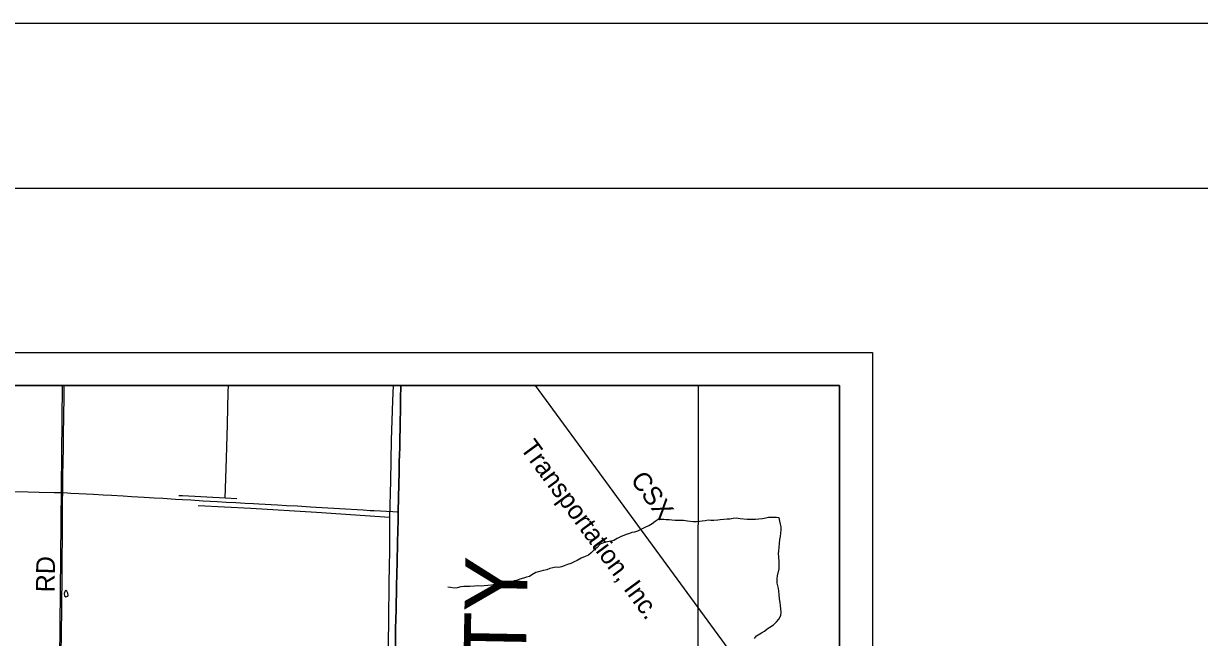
# Model space of a CAD drawing. Extents: x 0 to 34, y 0 to 22.
# Drawn here: x 6.42 to 9.993, y 20.135 to 22 of the extents above; entities that cross this region are included whole.
import ezdxf

# ---------------------------------------------------------------- set-up
doc = ezdxf.new("R2010")
doc.units = 0
for name, color, linetype in [('GM_X_City_Street', 7, 'Continuous'), ('GM_X_County_Road', 7, 'Continuous'), ('GM_X_County_Text', 7, 'Continuous'), ('GM_X_Minor_Lake', 7, 'Continuous'), ('GM_X_Minor_River', 7, 'Continuous'), ('GM_X_Rail_Line', 7, 'Continuous'), ('GM_X_Rail_Line_Text', 7, 'Continuous'), ('GM_X_Township_Road', 7, 'Continuous'), ('GM_X_Township_Road_Text', 7, 'Continuous'), ('GM_X_US_Route', 7, 'Continuous'), ('SH_Border', 7, 'Continuous'), ('SH_Cut_Line', 7, 'Continuous'), ('SH_Data', 7, 'Continuous')]:
    doc.layers.add(name, color=color, linetype=linetype)

msp = doc.modelspace()

# ---------------------------------------------------------------- linework, layer by layer
at = {"layer": 'GM_X_City_Street'}
msp.add_lwpolyline([(6.5392, 20.9), (5.527, 20.9), (5.5144, 20.0832), (6.5307, 20.0674)], close=True, dxfattribs=at)
at = {"layer": 'GM_X_County_Road'}
for points in [[(7.559, 20.516), (7.5591, 20.5235), (7.5596, 20.5509), (7.561, 20.6068), (7.5616, 20.6298), (7.5625, 20.6684), (7.563, 20.6883), (7.5638, 20.7125), (7.5655, 20.7958), (7.5659, 20.8188), (7.5659, 20.8449), (7.5661, 20.8636), (7.5668, 20.8953), (7.5669, 20.9)], [(7.5482, 19.9914), (7.5483, 19.9933), (7.5491, 20.0362), (7.5506, 20.1015), (7.5514, 20.1605), (7.5521, 20.1904), (7.5528, 20.2173), (7.5543, 20.2911), (7.5548, 20.3278), (7.556, 20.3619), (7.5564, 20.3806), (7.5567, 20.4036), (7.5571, 20.4228), (7.5579, 20.4589), (7.5585, 20.4894), (7.559, 20.516)]]:
    msp.add_lwpolyline(points, dxfattribs=at)
at = {"layer": 'GM_X_Minor_Lake'}
msp.add_line((6.5563, 20.2631), (6.5549, 20.2696), dxfattribs=at)
msp.add_lwpolyline([(6.5549, 20.2696), (6.5524, 20.2749), (6.549, 20.2773), (6.5467, 20.2758), (6.5435, 20.2683), (6.5448, 20.2611), (6.5493, 20.2579), (6.555, 20.2601), (6.5563, 20.2631)], dxfattribs=at)
at = {"layer": 'GM_X_Minor_River'}
for points in [[(7.0332, 20.5574), (7.0369, 20.678), (7.0407, 20.783), (7.0427, 20.8813), (7.0434, 20.9)], [(7.5437, 20.9), (7.5419, 20.8536), (7.5371, 20.7342), (7.5355, 20.6109), (7.5328, 20.4994), (7.5329, 20.3973), (7.5305, 20.3017), (7.5295, 20.186), (7.5269, 20.0494), (7.5234, 19.925), (7.5204, 19.8192)], [(7.0683, 20.5558), (7.0332, 20.5574), (6.9035, 20.5651), (6.8925, 20.5654)], [(7.5328, 20.4994), (7.3108, 20.5139), (7.1115, 20.5263), (6.9515, 20.5343)], [(8.7202, 20.231), (8.719, 20.2409), (8.7174, 20.2519), (8.7162, 20.2648), (8.7154, 20.275), (8.7139, 20.2838), (8.712, 20.2913), (8.7108, 20.2993), (8.7107, 20.3134), (8.7118, 20.3217), (8.7159, 20.3426), (8.7163, 20.3529), (8.7159, 20.3631), (8.715, 20.3802), (8.7146, 20.3885), (8.715, 20.398), (8.7161, 20.4075), (8.7186, 20.4318), (8.7209, 20.4417), (8.7223, 20.4619), (8.7227, 20.4706), (8.7207, 20.4785), (8.7188, 20.4876), (8.7161, 20.4979), (8.7085, 20.499), (8.7009, 20.4993), (8.693, 20.4989), (8.6842, 20.4992), (8.6755, 20.4973), (8.6653, 20.495), (8.6543, 20.4938), (8.6444, 20.4929), (8.6292, 20.4925), (8.6194, 20.4932), (8.5977, 20.4954), (8.5856, 20.4972), (8.5769, 20.4964), (8.5666, 20.4944), (8.5583, 20.494), (8.5484, 20.4932), (8.5374, 20.4916), (8.5298, 20.4908), (8.5181, 20.4896), (8.5086, 20.4903), (8.5002, 20.491), (8.4911, 20.4891), (8.465, 20.4863), (8.4555, 20.4855), (8.438, 20.4881), (8.4262, 20.4895), (8.4179, 20.4899), (8.4103, 20.4902), (8.4004, 20.4901), (8.3898, 20.4908), (8.3822, 20.4919), (8.3735, 20.4923), (8.3659, 20.4926), (8.3568, 20.493), (8.3484, 20.4929), (8.3393, 20.4872), (8.3306, 20.4803), (8.32, 20.4734), (8.3125, 20.4703), (8.3038, 20.4665), (8.2962, 20.4626), (8.2863, 20.458), (8.2765, 20.4549), (8.2689, 20.4534), (8.2613, 20.4507), (8.2511, 20.4472), (8.2344, 20.4403), (8.2238, 20.4349), (8.214, 20.4288), (8.2052, 20.4269), (8.195, 20.4253), (8.1829, 20.4222), (8.173, 20.418), (8.1636, 20.4084), (8.1549, 20.4015), (8.1454, 20.392), (8.1371, 20.3851), (8.1272, 20.3809), (8.1151, 20.3755), (8.103, 20.3686), (8.0939, 20.3644), (8.0829, 20.3598), (8.0735, 20.3563), (8.0636, 20.3525), (8.0549, 20.349), (8.0465, 20.3474), (8.0363, 20.3478), (8.0283, 20.3462), (8.0196, 20.3446), (8.0101, 20.3404), (7.9995, 20.3381), (7.9851, 20.3342), (7.9772, 20.3315), (7.965, 20.325), (7.9575, 20.3196), (7.9488, 20.3173), (7.9397, 20.3146)], [(7.9397, 20.3146), (7.9287, 20.3115), (7.9188, 20.308), (7.9112, 20.3065), (7.9006, 20.303), (7.8908, 20.2999), (7.8805, 20.2976), (7.8714, 20.2976), (7.8635, 20.2971), (7.8513, 20.2959), (7.8426, 20.2936), (7.8312, 20.292), (7.8198, 20.2912), (7.8111, 20.2908), (7.8001, 20.2915), (7.7902, 20.2907), (7.7766, 20.2895), (7.7663, 20.2898), (7.758, 20.2894), (7.7489, 20.2882), (7.7379, 20.2851), (7.7292, 20.2847), (7.7178, 20.2861), (7.7098, 20.2872)], [(8.6416, 20.1315), (8.6476, 20.1395), (8.6628, 20.1491), (8.6723, 20.1541), (8.6802, 20.161), (8.6878, 20.1656), (8.6987, 20.1725), (8.7086, 20.182), (8.7158, 20.19), (8.7218, 20.2018), (8.7229, 20.2117), (8.7217, 20.2216), (8.7202, 20.231)]]:
    msp.add_lwpolyline(points, dxfattribs=at)
at = {"layer": 'GM_X_Rail_Line'}
msp.add_lwpolyline([(8.9, 19.6389), (8.8604, 19.6932), (8.4181, 20.2972), (7.9759, 20.9)], dxfattribs=at)
at = {"layer": 'GM_X_Township_Road'}
msp.add_line((8.4697, 19.9905), (8.4711, 20.9), dxfattribs=at)
for points in [[(6.5395, 20.5746), (6.54, 20.6223), (6.5409, 20.6713), (6.5418, 20.7066), (6.542, 20.7127), (6.5423, 20.7526), (6.543, 20.8042), (6.5432, 20.8223), (6.5436, 20.8517), (6.5439, 20.8797), (6.5443, 20.9)], [(6.3942, 20.5779), (6.434, 20.5768), (6.4675, 20.5762), (6.5148, 20.575), (6.5353, 20.5747), (6.5395, 20.5746)], [(6.535, 20.0889), (6.5357, 20.1441), (6.536, 20.1628), (6.5361, 20.1753), (6.5364, 20.1945), (6.5366, 20.2031), (6.5367, 20.2127), (6.5367, 20.2169), (6.5367, 20.2249), (6.5371, 20.2456), (6.5373, 20.2698), (6.5375, 20.281), (6.5378, 20.3338), (6.5381, 20.382), (6.5381, 20.3851), (6.5384, 20.4274), (6.5385, 20.4349), (6.5386, 20.4541), (6.5389, 20.47), (6.5389, 20.4902), (6.5391, 20.5033), (6.5391, 20.5207), (6.5391, 20.533), (6.5393, 20.5579), (6.5395, 20.5685), (6.5395, 20.5746)], [(6.5395, 20.5746), (6.5538, 20.5739), (6.5638, 20.5735), (6.5886, 20.5721), (6.6333, 20.5695), (6.6625, 20.5677), (6.6873, 20.5666), (6.7233, 20.5644), (6.7482, 20.5631), (6.7871, 20.561), (6.8175, 20.559), (6.8436, 20.5574), (6.8821, 20.555), (6.9038, 20.5537), (6.9293, 20.5523), (6.9659, 20.5498), (7.0088, 20.5475), (7.0361, 20.5459), (7.0653, 20.5443), (7.0938, 20.5427), (7.1193, 20.5416), (7.1355, 20.5408), (7.1926, 20.5377), (7.2193, 20.536), (7.2528, 20.5342), (7.2919, 20.5318), (7.3801, 20.5267), (7.4527, 20.5221), (7.4732, 20.5206), (7.4856, 20.5199), (7.5421, 20.5168), (7.5554, 20.5162), (7.559, 20.516)]]:
    msp.add_lwpolyline(points, dxfattribs=at)
at = {"layer": 'GM_X_US_Route'}
for points in [[(7.5504, 20.102), (7.5511, 20.1611), (7.5519, 20.1909), (7.5526, 20.2178), (7.5541, 20.2916), (7.5545, 20.3283), (7.5557, 20.3625), (7.5562, 20.3811), (7.5565, 20.4041), (7.5569, 20.4234), (7.5577, 20.4595), (7.5583, 20.4899), (7.5588, 20.5166), (7.5589, 20.5241), (7.5593, 20.5515), (7.5608, 20.6074), (7.5614, 20.6304), (7.5623, 20.6689), (7.5628, 20.6888), (7.5635, 20.7131), (7.5652, 20.7964), (7.5656, 20.8193), (7.5657, 20.8455), (7.5659, 20.8641), (7.5666, 20.8958), (7.5667, 20.9), (2.1, 20.9)], [(8.9, 14.5091), (8.9, 20.9), (7.5667, 20.9), (7.5666, 20.8958), (7.5659, 20.8641), (7.5657, 20.8455), (7.5656, 20.8193), (7.5652, 20.7964), (7.5635, 20.7131), (7.5628, 20.6888), (7.5623, 20.6689), (7.5614, 20.6304), (7.5608, 20.6074), (7.5593, 20.5515), (7.5589, 20.5241), (7.5588, 20.5166), (7.5583, 20.4899), (7.5577, 20.4595), (7.5569, 20.4234), (7.5565, 20.4041), (7.5562, 20.3811), (7.5557, 20.3625), (7.5545, 20.3283), (7.5541, 20.2916), (7.5526, 20.2178), (7.5519, 20.1909), (7.5511, 20.1611), (7.5504, 20.102)]]:
    msp.add_lwpolyline(points, dxfattribs=at)
at = {"layer": 'SH_Border'}
msp.add_lwpolyline([(1.5, 21.5), (33.5, 21.5), (33.5, 0.5), (1.5, 0.5)], close=True, dxfattribs=at)
at = {"layer": 'SH_Cut_Line'}
msp.add_lwpolyline([(0, 0), (34, 0), (34, 22), (0, 22)], close=True, dxfattribs=at)
for points in [[(7.5504, 20.102), (7.5511, 20.1611), (7.5519, 20.1909), (7.5526, 20.2178), (7.5541, 20.2916), (7.5545, 20.3283), (7.5557, 20.3625), (7.5562, 20.3811), (7.5565, 20.4041), (7.5569, 20.4234), (7.5577, 20.4595), (7.5583, 20.4899), (7.5588, 20.5166), (7.5589, 20.5241), (7.5593, 20.5515), (7.5608, 20.6074), (7.5614, 20.6304), (7.5623, 20.6689), (7.5628, 20.6888), (7.5635, 20.7131), (7.5652, 20.7964), (7.5656, 20.8193), (7.5657, 20.8455), (7.5659, 20.8641), (7.5666, 20.8958), (7.5667, 20.9), (2.1, 20.9)], [(8.9, 14.1), (8.9, 20.9), (7.5667, 20.9), (7.5666, 20.8958), (7.5659, 20.8641), (7.5657, 20.8455), (7.5656, 20.8193), (7.5652, 20.7964), (7.5635, 20.7131), (7.5628, 20.6888), (7.5623, 20.6689), (7.5614, 20.6304), (7.5608, 20.6074), (7.5593, 20.5515), (7.5589, 20.5241), (7.5588, 20.5166), (7.5583, 20.4899), (7.5577, 20.4595), (7.5569, 20.4234), (7.5565, 20.4041), (7.5562, 20.3811), (7.5557, 20.3625), (7.5545, 20.3283), (7.5541, 20.2916), (7.5526, 20.2178), (7.5519, 20.1909), (7.5511, 20.1611), (7.5504, 20.102)]]:
    msp.add_lwpolyline(points, dxfattribs=at)
at = {"layer": 'SH_Data'}
for p, q in [((2, 21), (9, 21)), ((9, 21), (9, 14)), ((2.1, 20.9), (8.9, 20.9)), ((8.9, 20.9), (8.9, 14.1))]:
    msp.add_line(p, q, dxfattribs=at)

# ---------------------------------------------------------------- texts
at = {"layer": 'GM_X_County_Text'}
msp.add_text('SANDUSKY COUNTY', height=0.189394, rotation=88.9341, dxfattribs=at).set_placement((7.9054, 17.8465))
at = {"layer": 'GM_X_Rail_Line_Text'}
for s, height, rotation, p in [('Transportation, Inc.', 0.056629, 306.3101, (7.9275, 20.7096)), ('CSX', 0.05663, 306.183, (8.2624, 20.6136))]:
    msp.add_text(s, height=height, rotation=rotation, dxfattribs=at).set_placement(p)
at = {"layer": 'GM_X_Township_Road_Text'}
msp.add_text('RD', height=0.05682, rotation=89.5146, dxfattribs=at).set_placement((6.5151, 20.2717))

doc.saveas('drawing.dxf')
